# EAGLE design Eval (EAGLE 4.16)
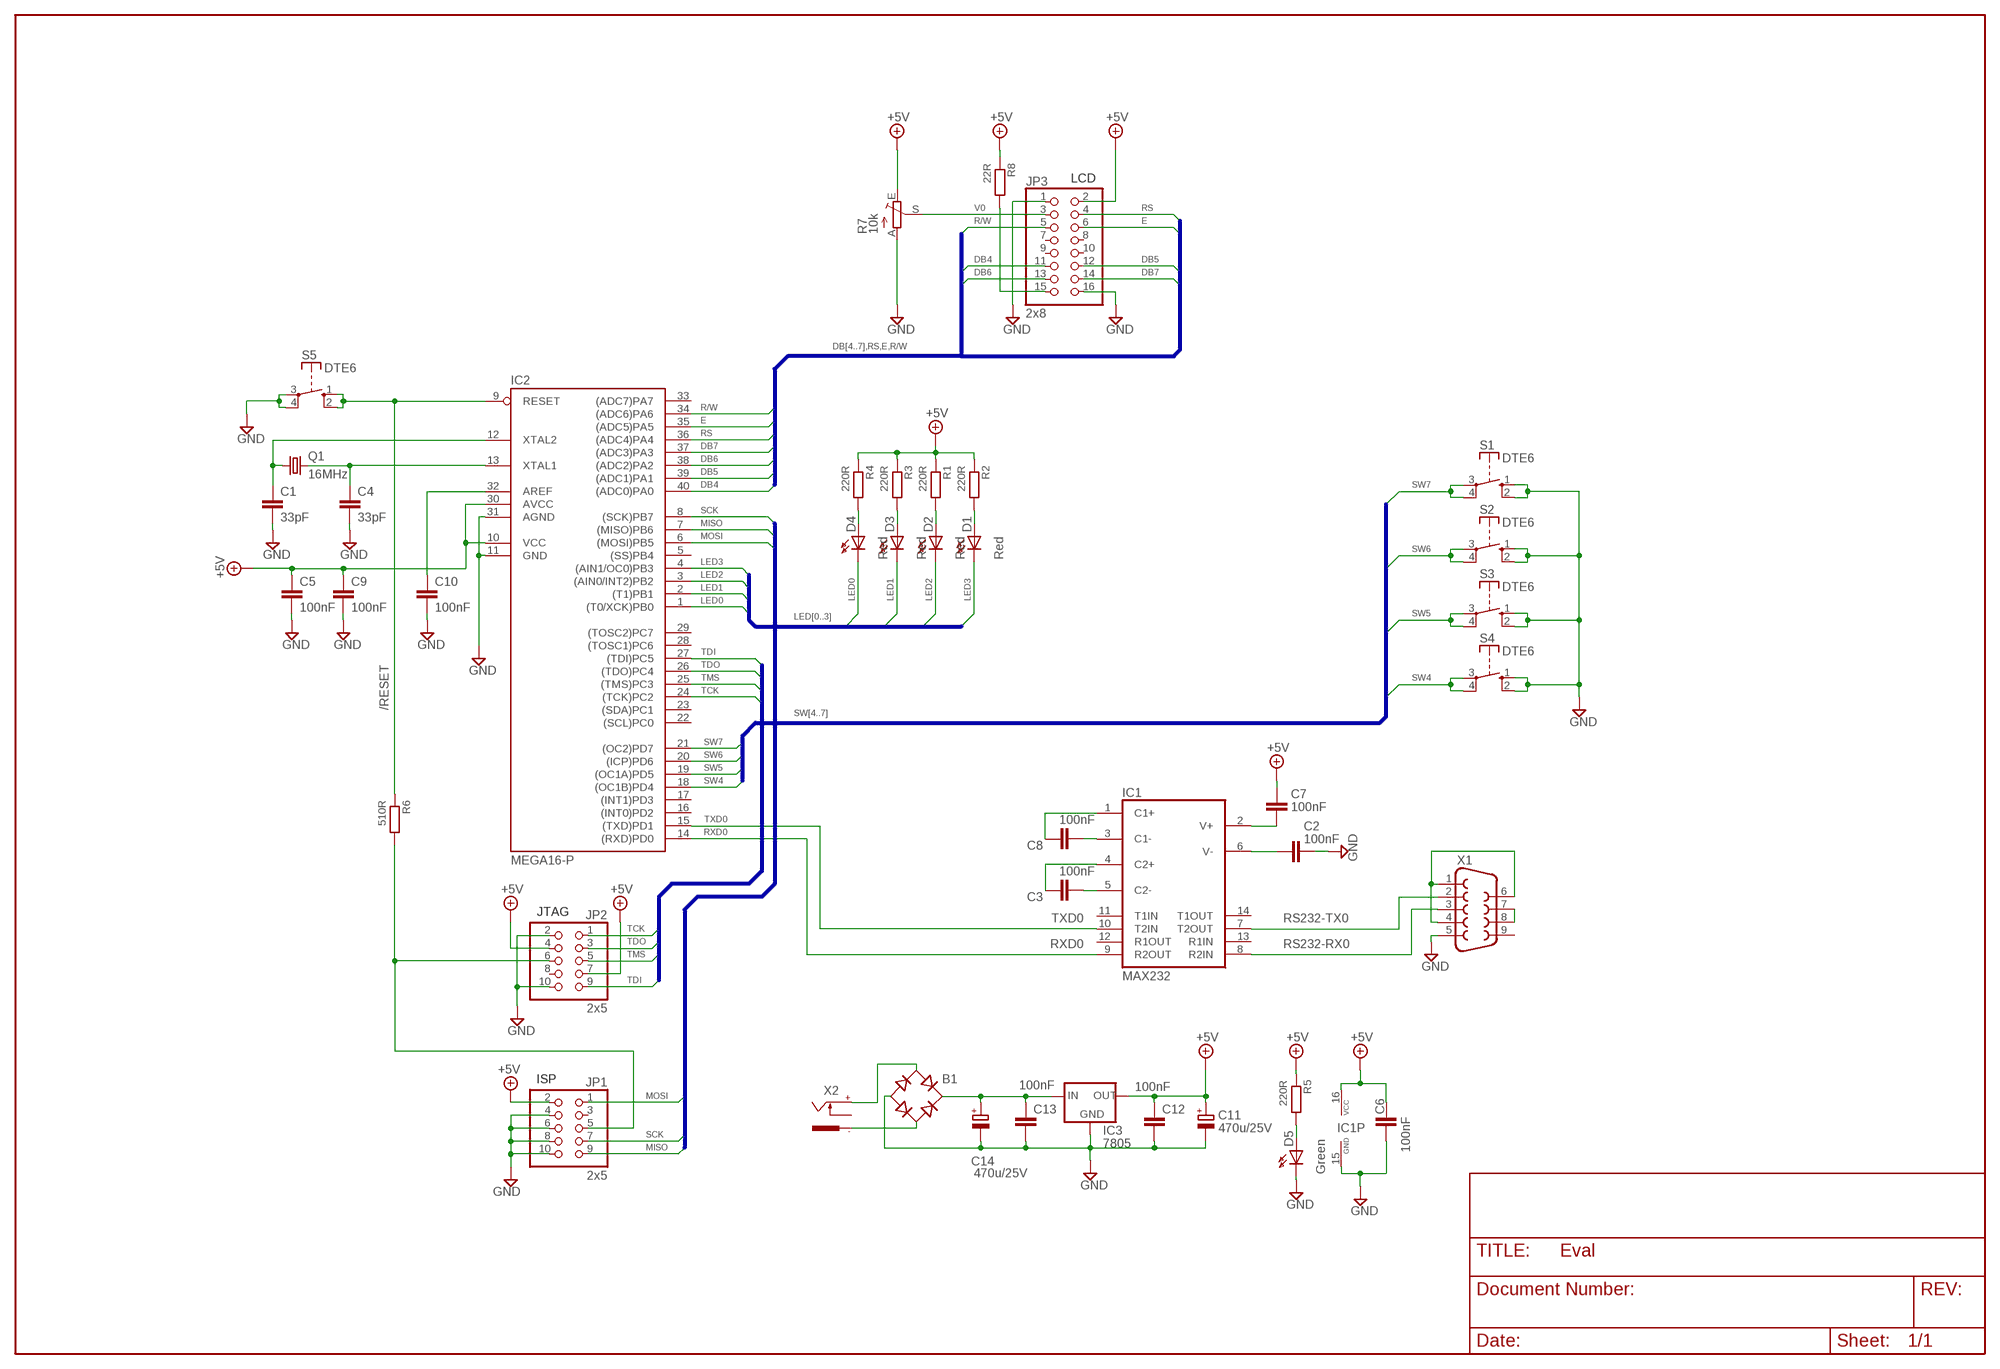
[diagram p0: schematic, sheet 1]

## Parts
B1  RB1A  [RB1A]
C1  33pF  C-EU025-024X044  [C025-024X044]
C2  100nF  C-EU025-024X044  [C025-024X044]
C3  100nF  C-EU025-024X044  [C025-024X044]
C4  33pF  C-EU025-024X044  [C025-024X044]
C5  100nF  C-EU025-024X044  [C025-024X044]
C6  100nF  C-EU025-024X044  [C025-024X044]
C7  100nF  C-EUC0402  [C0402]
C8  100nF  C-EU025-024X044  [C025-024X044]
C9  100nF  C-EU025-024X044  [C025-024X044]
C10  100nF  C-EU025-024X044  [C025-024X044]
C11  470u/25V  CPOL-EUE5-10.5  [E5-10,5]
C12  100nF  C-EU025-024X044  [C025-024X044]
C13  100nF  C-EU025-024X044  [C025-024X044]
C14  470u/25V  CPOL-EUE5-10.5  [E5-10,5]
D1  Red  LED3MM  [LED3MM]
D2  Red  LED3MM  [LED3MM]
D3  Red  LED3MM  [LED3MM]
D4  Red  LED3MM  [LED3MM]
D5  Green  LED3MM  [LED3MM]
IC1  MAX232  [DIL16]
IC2  MEGA16-P  [DIL40]
IC3  7805  78XXS  [78XXS]
JP1  2x5  PINHD-2X5  [2X05]
JP2  2x5  PINHD-2X5  [2X05]
JP3  2x8  PINHD-2X8  [2X08]
Q1  16MHz  CRYSTALHC49S  [HC49/S]
R1  220R  R-EU_0207/10  [0207/10@1]
R2  220R  R-EU_0207/10  [0207/10@1]
R3  220R  R-EU_0207/10  [0207/10@1]
R4  220R  R-EU_0207/10  [0207/10@1]
R5  220R  R-EU_M1206  [M1206]
R6  510R  R-EU_0207/10  [0207/10@1]
R7  10k  TRIM_EU-B64Y  [B64Y]
R8  22R  R-EU_0207/10  [0207/10@1]
S1  DTE6  [DTE6]
S2  DTE6  [DTE6]
S3  DTE6  [DTE6]
S4  DTE6  [DTE6]
S5  DTE6  [DTE6]
X1  F09H  [F09H]
X2  NEB21R  [NEB21R]

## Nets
+5V: C5.2 C6.1 C7.2 C9.2 C11.+ C12.2 IC1.16(VCC) IC2.10(VCC) IC2.30(AVCC) IC3.OUT JP1.2 JP2.4 JP2.7 JP3.2 R1.1 R2.1 R3.1 R4.1 R5.1 R7.E R8.1
/RESET: IC2.9(RESET) R6.1 S5.1(S) S5.2(S)
/RESET_ISP: JP1.5 JP2.6 R6.2
DB4: IC2.40((ADC0)PA0) JP3.11
DB5: IC2.39((ADC1)PA1) JP3.12
DB6: IC2.38((ADC2)PA2) JP3.13
DB7: IC2.37((ADC3)PA3) JP3.14
E: IC2.35((ADC5)PA5) JP3.6
GND: B1.- C1.1 C2.1 C4.1 C5.1 C6.2 C9.1 C10.1 C11.- C12.1 C13.1 C14.- D5.K(C) IC1.15(GND) IC2.11(GND) IC2.31(AGND) IC3.GND JP1.4 JP1.6 JP1.8 JP1.10 JP2.2 JP2.10 JP3.1 JP3.16 R7.A S1.1(S) S1.2(S) S2.1(S) S2.2(S) S3.1(S) S3.2(S) S4.1(S) S4.2(S) S5.3(P) S5.4(P) X1.5
LED0: D4.K(C) IC2.1((T0/XCK)PB0)
LED1: D3.K(C) IC2.2((T1)PB1)
LED2: D2.K(C) IC2.3((AIN0/INT2)PB2)
LED3: D1.K(C) IC2.4((AIN1/OC0)PB3)
LED-A: JP3.15 R8.2
MISO: IC2.7((MISO)PB6) JP1.9
MOSI: IC2.6((MOSI)PB5) JP1.1
N$1: D4.A R4.2
N$2: D3.A R3.2
N$3: D2.A R1.2
N$4: D1.A R2.2
N$5: C10.2 IC2.32(AREF)
N$8: C2.2 IC1.6(V-)
N$9: C7.1 IC1.2(V+)
N$21: C3.2 IC1.5(C2-)
N$23: C3.1 IC1.4(C2+)
N$24: C8.2 IC1.3(C1-)
N$25: C8.1 IC1.1(C1+)
N$29: C4.2 IC2.13(XTAL1) Q1.2
N$30: C1.2 IC2.12(XTAL2) Q1.1
N$44: X1.1 X1.4 X1.6
N$45: D5.A R5.2
N$46: B1.AC2 X2.-
N$47: X1.7 X1.8
N$68: B1.AC1 X2.+
N$73: B1.+ C13.2 C14.+ IC3.IN
R/W: IC2.34((ADC6)PA6) JP3.5
RS: IC2.36((ADC4)PA4) JP3.4
RS232-RX0: IC1.8(R2IN) X1.3
RS232-TX0: IC1.7(T2OUT) X1.2
RXD0: IC1.9(R2OUT) IC2.14((RXD)PD0)
SCK: IC2.8((SCK)PB7) JP1.7
SW4: IC2.18((OC1B)PD4) S4.3(P) S4.4(P)
SW5: IC2.19((OC1A)PD5) S3.3(P) S3.4(P)
SW6: IC2.20((ICP)PD6) S2.3(P) S2.4(P)
SW7: IC2.21((OC2)PD7) S1.3(P) S1.4(P)
TCK: IC2.24((TCK)PC2) JP2.1
TDI: IC2.27((TDI)PC5) JP2.9
TDO: IC2.26((TDO)PC4) JP2.3
TMS: IC2.25((TMS)PC3) JP2.5
TXD0: IC1.10(T2IN) IC2.15((TXD)PD1)
V0: JP3.3 R7.S
Unconnected: IC1.11(T1IN) IC1.12(R1OUT) IC1.13(R1IN) IC1.14(T1OUT) IC2.5((SS)PB4) IC2.16((INT0)PD2) IC2.17((INT1)PD3) IC2.22((SCL)PC0) IC2.23((SDA)PC1) IC2.28((TOSC1)PC6) IC2.29((TOSC2)PC7) IC2.33((ADC7)PA7) JP1.3 JP2.8 JP3.7 JP3.8 JP3.9 JP3.10 X1.9 X2.C

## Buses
SCK,MISO,MOSI
DB[4..7],RS,E,R/W
LED[0..3]
TDI,TDO,TMS,TCK
SW[4..7]

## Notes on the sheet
- LCD
- JTAG
- ISP

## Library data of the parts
B1 = rectifier:RB1A: RECTIFIER 1 A
C1-C10 C12 C13 = rcl:C-EU: CAPACITOR, European symbol
C11 C14 = rcl:CPOL-EU: POLARIZED CAPACITOR, European symbol
D1-D5 = led:LED3MM: LED
IC1 = maxim:MAX232: RS232 TRANSEIVER
IC2 = avr:MEGA16-P: MICROCONTROLLER 16 Kbytes FLASH 1 kbytes SRAM 512 bytes EEPROM USART 8-channel 10 bit ADC
IC3 = v-reg:78XXS: VOLTAGE REGULATOR
JP1 JP2 = pinhead:PINHD-2X5: PIN HEADER
JP3 = pinhead:PINHD-2X8: PIN HEADER
Q1 = crystal:CRYSTAL: CRYSTAL
R1-R6 R8 = rcl:R-EU_: RESISTOR, European symbol
R7 = pot:TRIM_EU-: POTENTIOMETER
S1-S5 = switch-misc:DT: ITT SWITCH
X1 = con-subd:F09H: HARTING SUB-D
X2 = con-lumberg:NEB21R: CONNECTOR

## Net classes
1 pup: width 1 mm, drill 254 mm, clearance 0.254 mm

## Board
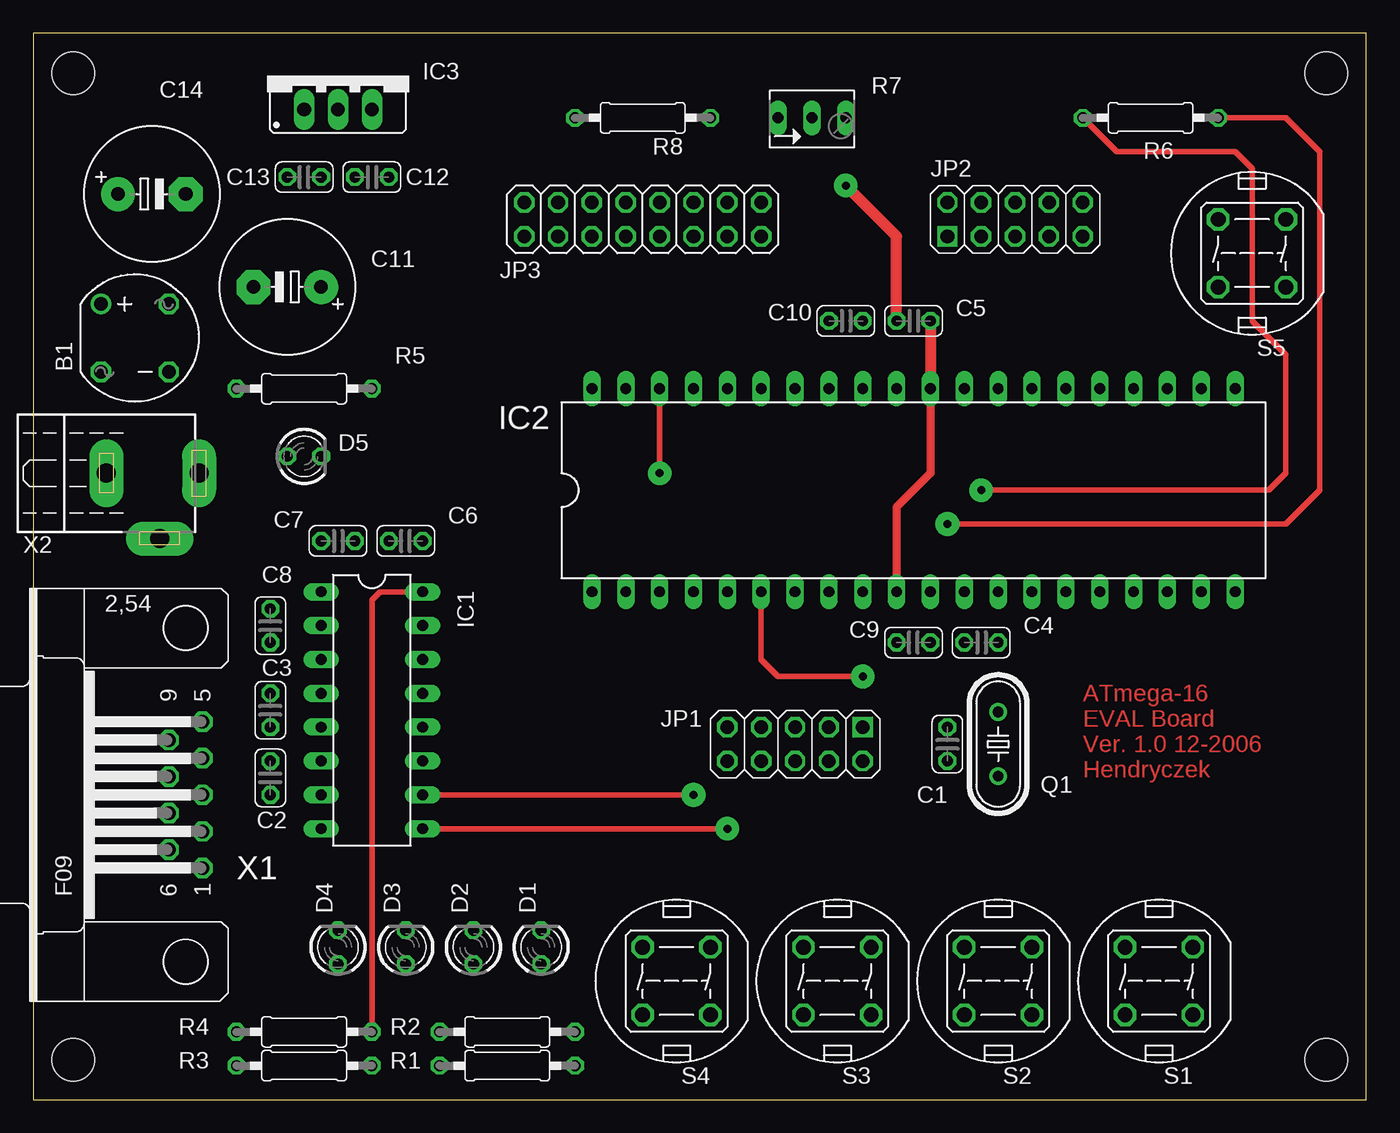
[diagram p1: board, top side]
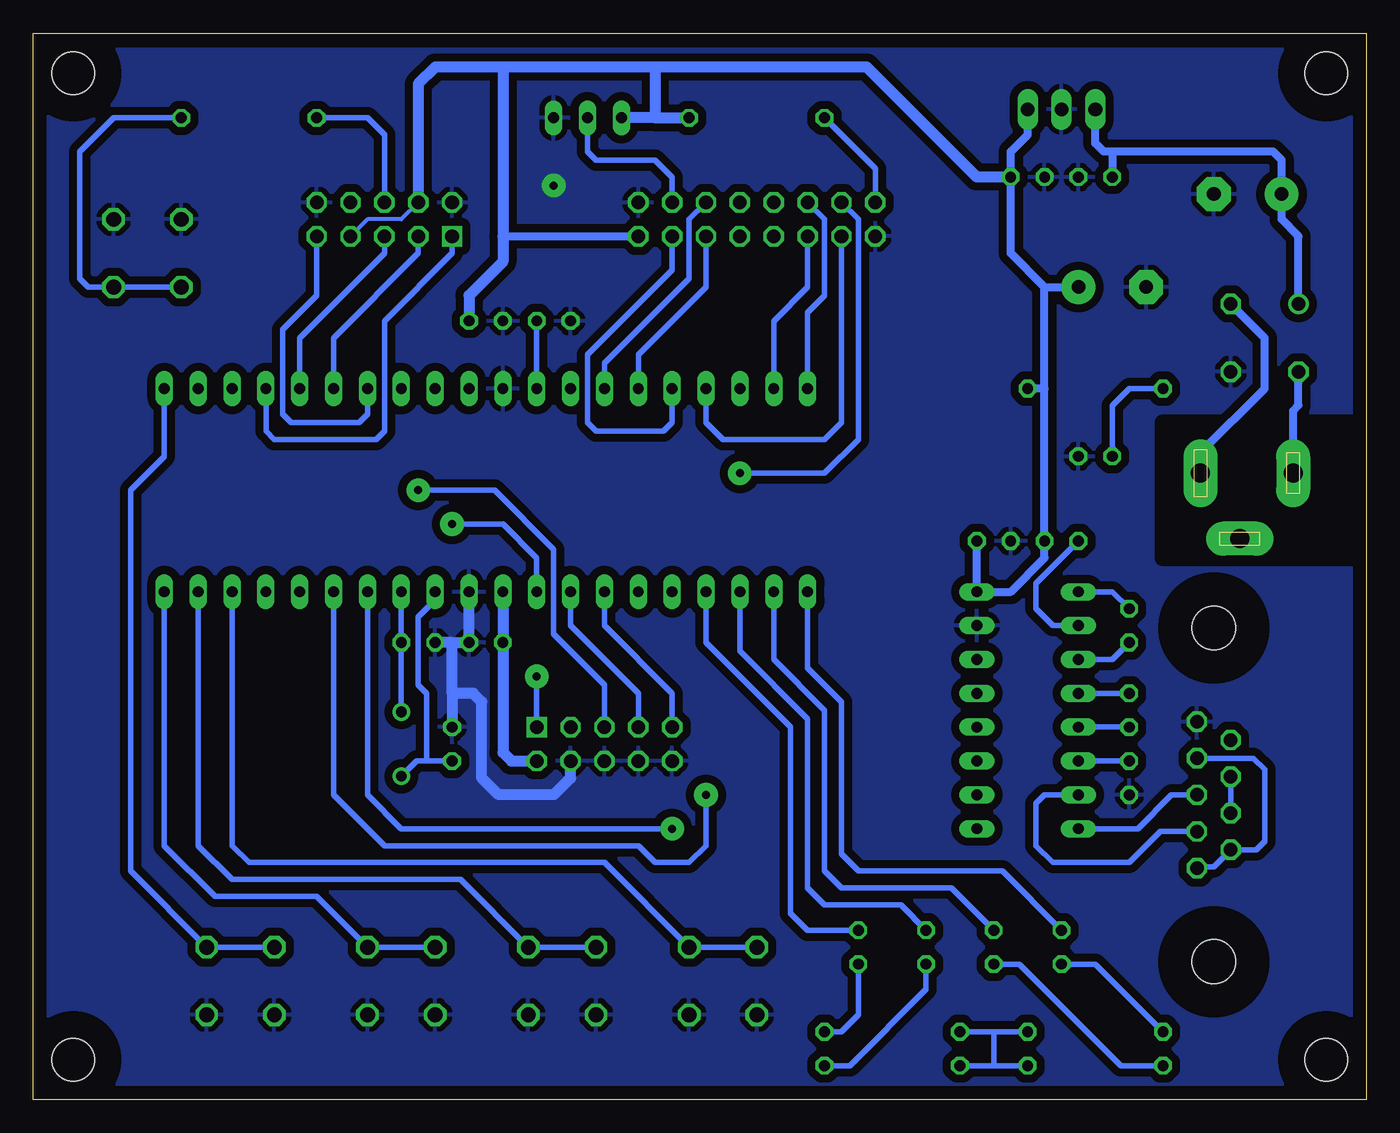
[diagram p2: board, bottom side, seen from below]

Size 100 x 80 mm. Coordinates in mm from the lower left corner, seen from the top.
Outline: 0,0 100,0 100,80 0,80 0,0
Copper layers ([2:1+(((2*4)+(6*8))+((9*11)+(13*15)))+16:15]): Top 0.035mm / dielectric 0.15mm / layer 2 0.035mm / dielectric 0.2mm / layer 4 0.035mm / dielectric 0.15mm / layer 6 0.035mm / dielectric 0.2mm / layer 8 0.035mm / dielectric 0.15mm / layer 9 0.035mm / dielectric 0.2mm / layer 11 0.035mm / dielectric 0.15mm / layer 13 0.035mm / dielectric 0.2mm / layer 15 0.035mm / dielectric 0.15mm / Bottom 0.035mm
Design rules "Eval": minimum track width 8mil, minimum drill 23mil, track to track 8mil, track to pad 8mil, pad to pad 8mil, via to via 8mil, smd to smd 8mil, copper to edge 40mil, drill to drill 8mil, minimum pad ring 10mil, minimum via ring 8mil, stop-mask expansion 4mil, vias tented up to drill 0mil, thermal gap 16mil
Holes 3.2 mm at 3,3 97,3 97,77 3,77
bRestrict: area 0,40.6 to 15.2,50.8; area 0,74 to 6,80; area 94,74 to 100,80; area 94,0 to 100,6; area 0,0 to 6,6

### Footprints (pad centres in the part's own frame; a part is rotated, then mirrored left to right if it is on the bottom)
RB1A = drill 1.016 round: + -2.54,2.54 | drill 1.016 octagon: - 2.54,-2.54; AC1 2.54,2.54; AC2 -2.54,-2.54
C025-024X044 = drill 0.813 octagon: 1 -1.27,0; 2 1.27,0
E5-10,5 = drill 1.016 pad 2.54 round: + -2.54,0 | drill 1.016 pad 2.54 octagon: - 2.54,0
LED3MM = drill 0.813 octagon: A -1.27,0; K 1.27,0
DIL16 = drill 0.813 long: 1 -8.89,-3.81; 2 -6.35,-3.81; 3 -3.81,-3.81; 4 -1.27,-3.81; 5 1.27,-3.81; 6 3.81,-3.81; 7 6.35,-3.81; 8 8.89,-3.81; 9 8.89,3.81; 10 6.35,3.81; 11 3.81,3.81; 12 1.27,3.81; 13 -1.27,3.81; 14 -3.81,3.81; 15 -6.35,3.81; 16 -8.89,3.81
DIL40 = drill 0.813 long: 1 -24.13,-7.62; 2 -21.59,-7.62; 3 -19.05,-7.62; 4 -16.51,-7.62; 5 -13.97,-7.62; 6 -11.43,-7.62; 7 -8.89,-7.62; 8 -6.35,-7.62; 9 -3.81,-7.62; 10 -1.27,-7.62; 11 1.27,-7.62; 12 3.81,-7.62; 13 6.35,-7.62; 14 8.89,-7.62; 15 11.43,-7.62; 16 13.97,-7.62; 17 16.51,-7.62; 18 19.05,-7.62; 19 21.59,-7.62; 20 24.13,-7.62; 21 24.13,7.62; 22 21.59,7.62; 23 19.05,7.62; 24 16.51,7.62; 25 13.97,7.62; 26 11.43,7.62; 27 8.89,7.62; 28 6.35,7.62; 29 3.81,7.62; 30 1.27,7.62; 31 -1.27,7.62; 32 -3.81,7.62; 33 -6.35,7.62; 34 -8.89,7.62; 35 -11.43,7.62; 36 -13.97,7.62; 37 -16.51,7.62; 38 -19.05,7.62; 39 -21.59,7.62; 40 -24.13,7.62
78XXS = drill 1.016 long: GND 0,-2.54; IN -2.54,-2.54; OUT 2.54,-2.54
2X05 = drill 1.016 square: 1 -5.08,-1.27 | drill 1.016 octagon: 2 -5.08,1.27; 3 -2.54,-1.27; 4 -2.54,1.27; 5 0,-1.27; 6 0,1.27; 7 2.54,-1.27; 8 2.54,1.27; 9 5.08,-1.27; 10 5.08,1.27
2X08 = drill 1.016 octagon: 1 -8.89,-1.27; 2 -8.89,1.27; 3 -6.35,-1.27; 4 -6.35,1.27; 5 -3.81,-1.27; 6 -3.81,1.27; 7 -1.27,-1.27; 8 -1.27,1.27; 9 1.27,-1.27; 10 1.27,1.27; 11 3.81,-1.27; 12 3.81,1.27; 13 6.35,-1.27; 14 6.35,1.27; 15 8.89,-1.27; 16 8.89,1.27
HC49/S = drill 0.813 round: 1 -2.413,0; 2 2.413,0
0207/10@1 = drill 0.813 octagon: 1 -5.08,0; 2 5.08,0
B64Y = drill 0.813 long: A 2.54,0; E -2.54,0; S 0,0
DTE6 = drill 1.118 octagon: 1 -2.54,2.54; 2 2.54,2.54; 3 2.54,-2.54; 4 -2.54,-2.54
F09H = drill 1.016 octagon: 1 -5.486,-1.27; 2 -2.743,-1.27; 3 0,-1.27; 4 2.743,-1.27; 5 5.486,-1.27; 6 -4.115,1.27; 7 -1.372,1.27; 8 1.372,1.27; 9 4.115,1.27 | hole 3.302: -12.522,0; 12.522,0
NEB21R = drill 1.422 pad 2.54 long: + 0,7.35; - 0,0.398; C 4.9,4.4

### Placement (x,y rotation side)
B1  7.62,57.15 0 top
C1  68.58,26.67 270 top
C2  17.78,24.13 90 top
C3  17.78,29.21 270 top
C4  71.12,34.29 0 top
C5  66.04,58.42 0 top
C6  27.94,41.91 180 top
C7  100nF  [C025-024X044]  22.86,41.91 0 top
C8  17.78,35.56 270 top
C9  66.04,34.29 180 top
C10  60.96,58.42 0 top
C11  19.05,60.96 180 top
C12  25.4,69.22 0 top
C13  20.32,69.22 180 top
C14  8.89,67.94 0 top
D1  38.1,11.43 90 top
D2  33.02,11.43 90 top
D3  27.94,11.43 90 top
D4  22.86,11.43 90 top
D5  20.32,48.26 0 top
IC1  25.4,29.21 270 top
IC2  66.04,45.72 0 top
IC3  22.86,76.83 0 top
JP1  57.15,26.67 180 top
JP2  73.66,66.04 0 top
JP3  45.72,66.04 180 top
Q1  72.39,26.67 90 top
R1  35.56,2.54 0 top
R2  35.56,5.08 0 top
R3  20.32,2.54 180 top
R4  20.32,5.08 180 top
R5  220R  [0207/10@1]  20.32,53.34 180 top
R6  83.82,73.66 180 top
R7  58.42,73.66 0 top
R8  45.72,73.66 180 top
S1  84.45,8.89 180 top
S2  72.39,8.89 180 top
S3  60.33,8.89 180 top
S4  48.26,8.89 180 top
S5  91.44,63.5 180 top
X1  11.43,22.86 90 top
X2  5.08,46.99 270 top

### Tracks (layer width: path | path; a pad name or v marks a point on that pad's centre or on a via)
+5V
  Top 0.406: R4.1 25.4,37.47 26.04,38.1 IC1.16
  Top 0.61: IC2.10 64.77,44.45 67.31,46.99 IC2.30
  Top 0.813: C5.2 IC2.30
  Bottom 0.305: JP2.7 74.93,66.04 72.39,66.04 JP2.4
  Bottom 0.406: R3.1 27.94,2.54 | 27.94,2.54 R1.1 | 27.94,5.08 R4.1 | 27.94,5.08 R2.1 | 27.94,2.54 27.94,5.08
  Bottom 0.61: C6.1 IC1.16 26.67,38.1 24.13,40.64 C7.2 24.13,53.34 | 24.13,53.34 24.13,60.96 | 24.13,60.96 C11.+ | 24.13,53.34 R5.1 | 24.13,60.96 26.67,63.5 C12.2 26.67,71.12 25.4,72.39 IC3.OUT | 64.77,64.77 JP3.2
  Bottom 0.813: JP1.2 64.14,25.4 64.77,26.04 C9.2 IC2.10 | 53.34,73.66 R7.E | 53.34,77.47 53.34,73.66 | 53.34,77.47 37.47,77.47 29.21,69.22 C12.2 | 53.34,73.66 R8.1 | 53.34,77.47 64.77,77.47 | 64.77,77.47 64.77,64.77 64.77,62.87 67.31,60.33 C5.2 | JP2.4 71.12,76.2 69.85,77.47 64.77,77.47
/RESET  (via drill 0.6 pad 1.78)
  Top 0.406: v68.58,43.18 93.98,43.18 96.52,45.72 96.52,71.12 93.98,73.66 R6.1
  Bottom 0.406: IC2.9 62.23,40.64 64.77,43.18 v68.58,43.18 | S5.2 S5.1 95.89,60.96 96.52,61.59 96.52,71.12 93.98,73.66 R6.1
/RESET_ISP  (via drill 0.6 pad 1.78)
  Top 0.406: v71.12,45.72 92.71,45.72 93.98,46.99 93.98,55.88 91.44,58.42 91.44,69.85 90.17,71.12 81.28,71.12 R6.2
  Bottom 0.406: JP1.5 57.15,31.11 60.96,34.92 60.96,41.27 65.41,45.72 v71.12,45.72 | JP2.6 73.66,72.39 74.93,73.66 R6.2
DB4
  Bottom 0.406: IC2.40 41.91,59.05 40.64,60.33 40.64,66.04 JP3.11
DB5
  Bottom 0.406: JP3.12 41.91,60.96 44.45,58.42 IC2.39
DB6  (via drill 0.6 pad 1.78)
  Top 0.406: v46.99,46.99 IC2.38
  Bottom 0.406: v46.99,46.99 40.64,46.99 38.1,49.53 38.1,66.04 JP3.13
DB7
  Bottom 0.406: JP3.14 39.37,50.8 40.64,49.53 48.26,49.53 49.53,50.8 IC2.37
E
  Bottom 0.406: IC2.35 54.61,55.88 49.53,60.96 JP3.6
GND  (via drill 0.6 pad 1.78)
  Top 0.813: C5.1 64.77,64.77 v60.96,68.58
  Bottom 0.813: IC2.11 C9.1 68.58,34.29 | 68.58,30.48 C1.1 | 68.58,30.48 68.58,34.29 | 68.58,34.29 C4.1 | JP1.4 59.69,24.13 60.96,22.86 65.09,22.86 66.36,24.13 66.36,29.84 66.99,30.48 68.58,30.48
  pour Bottom (isolate 0.61): 0.64,0.64 0.64,79.38 99.69,79.38 99.69,0.64
LED0
  Bottom 0.406: IC2.1 41.91,32.38 39.37,29.84 39.37,18.41 38.1,17.14 27.3,17.14 D4.K
LED1
  Bottom 0.406: IC2.2 44.45,33.02 40.64,29.21 40.64,17.14 39.37,15.88 31.11,15.88 D3.K
LED2
  Bottom 0.406: IC2.3 46.99,33.66 41.91,28.57 41.91,15.88 40.64,14.61 34.92,14.61 D2.K
LED3
  Bottom 0.406: IC2.4 49.53,34.29 43.18,27.94 43.18,13.97 41.91,12.7 D1.K
LED-A
  Bottom 0.406: JP3.15 36.83,69.85 R8.2
MISO
  Bottom 0.406: JP1.9 52.07,30.48 57.15,35.56 IC2.7
MOSI  (via drill 0.6 pad 1.78)
  Top 0.406: v62.23,31.75 55.88,31.75 54.61,33.02 IC2.6
  Bottom 0.406: v62.23,31.75 JP1.1
N$1
  Bottom 0.406: D4.A 20.32,10.16 R4.2
N$2
  Bottom 0.406: D3.A 26.04,10.16 18.41,2.54 R3.2
N$3
  Bottom 0.406: D2.A 33.02,8.26 38.73,2.54 R1.2
N$4
  Bottom 0.406: R2.2 39.37,5.08 38.1,6.35 D1.A
N$5
  Bottom 0.406: IC2.32 C10.2
N$8
  Bottom 0.406: C2.2 IC1.6
N$9
  Bottom 0.406: IC1.2 23.5,35.56 24.77,36.83 24.77,38.73 C7.1
N$21
  Bottom 0.406: C3.2 IC1.5
N$23
  Bottom 0.406: C3.1 IC1.4
N$24
  Bottom 0.406: C8.2 19.05,33.02 IC1.3
N$25
  Bottom 0.406: C8.1 19.05,38.1 IC1.1
N$29
  Bottom 0.406: Q1.2 C4.2 IC2.13
N$30
  Bottom 0.406: IC2.12 69.85,37.47 71.12,36.2 71.12,31.11 70.48,30.48 70.48,25.4 | 70.48,25.4 C1.2 | Q1.1 71.25,25.4 70.48,25.4
N$44
  Bottom 0.406: X1.1 12.7,17.46 11.44,17.46 X1.6 8.24,18.75 7.62,19.37 7.62,24.77 8.46,25.6 X1.4
N$45
  Bottom 0.406: D5.A 19.05,52.07 17.78,53.34 R5.2
N$46
  Bottom 0.61: X2.- 5.48,51.67 5.08,52.07 B1.AC2
N$47
  Bottom 0.406: X1.7 X1.8
N$68
  Bottom 0.61: X2.+ 12.43,48.53 7.62,53.34 7.62,57.15 B1.AC1
N$73
  Bottom 0.61: B1.+ 5.08,64.77 6.35,66.04 C14.+ 6.35,70.48 6.99,71.12 19.05,71.12 | 19.05,71.12 C13.2 | 19.05,71.12 19.68,71.12 20.32,71.75 IC3.IN
R/W
  Bottom 0.406: JP3.5 50.8,66.04 50.8,61.59 57.15,55.24 IC2.34
RS
  Bottom 0.406: JP3.4 52.07,62.23 58.42,55.88 58.42,50.8 57.78,50.16 52.7,50.16 52.07,50.8 IC2.36
RS232-RX0
  Bottom 0.406: X1.3 14.61,22.86 17.14,20.32 IC1.8
RS232-TX0
  Bottom 0.406: IC1.7 24.13,22.86 24.77,22.23 24.77,19.05 23.5,17.78 17.78,17.78 15.44,20.12 X1.2
RXD0  (via drill 0.6 pad 1.78)
  Top 0.406: IC1.9 v52.07,20.32
  Bottom 0.406: v52.07,20.32 72.39,20.32 74.93,22.86 IC2.14
SCK
  Bottom 0.406: JP1.7 54.61,30.48 59.69,35.56 IC2.8
SW4
  Bottom 0.406: IC2.18 85.09,19.05 83.82,17.78 57.15,17.78 S4.4 S4.3
SW5
  Bottom 0.406: IC2.19 87.63,19.05 85.09,16.51 67.94,16.51 S3.4 S3.3
SW6
  Bottom 0.406: IC2.20 90.17,19.05 86.36,15.24 78.74,15.24 S2.4 S2.3
SW7
  Bottom 0.406: IC2.21 90.17,48.26 92.71,45.72 92.71,17.14 S1.4 S1.3
TCK
  Bottom 0.406: JP2.1 68.58,63.5 73.66,58.42 73.66,50.16 74.3,49.53 81.92,49.53 82.55,50.16 IC2.24
TDI
  Bottom 0.406: IC2.27 74.93,51.44 75.56,50.8 80.64,50.8 81.28,51.44 81.28,57.78 78.74,60.33 JP2.9
TDO
  Bottom 0.406: JP2.3 71.12,63.5 77.47,57.15 IC2.26
TMS
  Bottom 0.406: JP2.5 73.66,63.5 80.01,57.15 IC2.25
TXD0  (via drill 0.6 pad 1.78)
  Top 0.406: IC1.10 v49.53,22.86
  Bottom 0.406: IC2.15 77.47,22.86 73.66,19.05 54.61,19.05 53.34,17.78 50.8,17.78 49.53,19.05 v49.53,22.86
V0
  Bottom 0.406: JP3.3 52.07,69.22 53.34,70.48 57.78,70.48 58.42,71.12 R7.S

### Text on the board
Top: ATmega-16 | EVAL Board | Ver. 1.0 12-2006 | Hendryczek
